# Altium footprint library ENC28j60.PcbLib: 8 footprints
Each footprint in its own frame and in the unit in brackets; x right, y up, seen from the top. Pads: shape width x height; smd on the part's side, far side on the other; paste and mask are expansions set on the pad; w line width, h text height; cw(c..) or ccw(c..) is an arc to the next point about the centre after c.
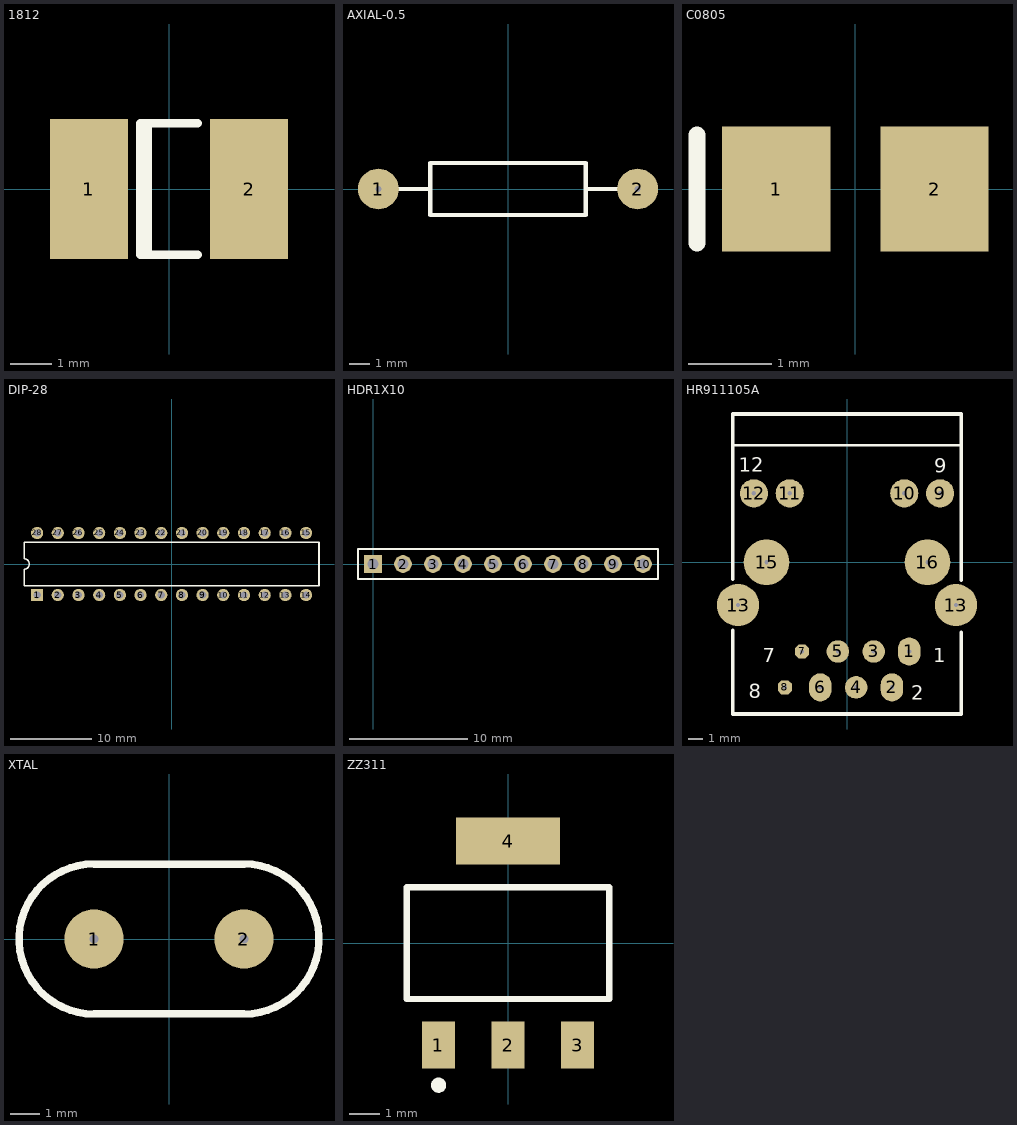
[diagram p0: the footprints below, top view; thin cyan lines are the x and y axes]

## 1812 [mm] "Chip Capacitor; Body 4.5 x 3.2 mm (LxW typ)"
height 1.1
pads (2):
  rect 1.9x3.4 smd: 1(-1.95,0) 2(1.95,0)
Top Overlay:
  lines w0.2: -0.51,-1.6 -0.51,1.6 ; 0.7,-1.6 -0.7,-1.6 -0.7,1.6 0.7,1.6

## AXIAL-0.5 [mm] "Semiconductor Resistor; 2 Leads"
height 2.54
pads (2):
  round 2 hole 0.3: 1(-6.35,0) 2(6.35,0)
Top Overlay:
  lines w0.2: -5.334,0 -3.81,0 ; 3.81,0 5.334,0 ; -3.81,-1.27 3.81,-1.27 3.81,1.27 -3.81,1.27 -3.81,-1.27

## C0805 [mm] "Chip Capacitor; Body 2.0 x 1.2 mm (LxW typ)"
height 1.1
pads (2):
  rect 1.3x1.5 smd: 1(-0.95,0) 2(0.95,0)
Top Overlay:
  lines w0.2: -1.9,-0.65 -1.9,0.65

## DIP-28 [mm] "DIP; 28 Leads; Row Spacing 7.62 mm; Pitch 2.54 mm"
height 5.33
pads (28):
  rect 1.5x1.5 hole 0.9: 1(-16.51,-3.81)
  round 1.5 hole 0.9: 2(-13.97,-3.81) 3(-11.43,-3.81) 4(-8.89,-3.81) 5(-6.35,-3.81) 6(-3.81,-3.81) 7(-1.27,-3.81) 8(1.27,-3.81) 9(3.81,-3.81) 10(6.35,-3.81) 11(8.89,-3.81) 12(11.43,-3.81) 13(13.97,-3.81) 14(16.51,-3.81) 15(16.51,3.81) 16(13.97,3.81) 17(11.43,3.81) 18(8.89,3.81) 19(6.35,3.81) 20(3.81,3.81) 21(1.27,3.81) 22(-1.27,3.81) 23(-3.81,3.81) 24(-6.35,3.81) 25(-8.89,3.81) 26(-11.43,3.81) 27(-13.97,3.81) 28(-16.51,3.81)
Top Overlay:
  lines w0.2: -18.1,-2.65 18.1,-2.65 18.1,2.65 -18.1,2.65 -18.1,0.635 cw(c-18.1,0) -18.1,-0.635 -18.1,-2.65

## HDR1X10 [mm] "Connector; Header; 10 Position"
height 5.08
pads (10):
  rect 1.5x1.5 hole 0.9: 1(0,0)
  round 1.5 hole 0.9: 2(2.54,0) 3(5.08,0) 4(7.62,0) 5(10.16,0) 6(12.7,0) 7(15.24,0) 8(17.78,0) 9(20.32,0) 10(22.86,0)
Top Overlay:
  lines w0.2: -1.27,-1.27 24.13,-1.27 24.13,1.27 0.635,1.27 -1.27,1.27 -1.27,-1.27

## HR911105A [mm] "HR911105A 带网络变压器及LED的一体化RJ45插座"
height 13.4
pads (16):
  oval 1.6x2 hole 0.3: 1(4.425,-6.35) 2(3.2,-8.9) 6(-1.9,-8.9)
  round 1.6 hole 0.3: 3(1.9,-6.35) 4(0.65,-8.9) 5(-0.65,-6.35)
  oct 1x1 hole 0.3: 7(-3.2,-6.35) 8(-4.425,-8.9)
  round 2 hole 0.3: 9(6.625,4.9) 10(4.075,4.9) 11(-4.075,4.9) 12(-6.625,4.9)
  round 3 hole 0.3: 13(-7.75,-3.05) 13(7.75,-3.05)
  round 3.25 hole 0.3: 15(-5.725,0) 16(5.725,0)
Top Overlay:
  lines w0.2: -8.128,8.325 8.078,8.325
  lines w0.254: -8.128,-4.847 -8.128,-10.795 8.128,-10.795 8.128,-4.978 ; -8.128,-1.203 -8.128,10.541 8.128,10.541 8.128,-1.297
  text "12" at -7.7,6.425 h1
  text "9" at 6.2,6.35 h1
  text "1" at 6.125,-7.125 h1
  text "7" at -5.975,-7.1 h1
  text "2" at 4.572,-9.779 h1
  text "8" at -6.975,-9.675 h1

## XTAL [mm] "晶振"
height 5.08
pads (2):
  round 2 hole 0.3: 1(-2.54,0) 2(2.54,0)
Top Overlay:
  lines w0.254: -2.54,-2.54 cw(c-2.54,0) -2.54,2.54 2.54,2.54 cw(c2.54,0) 2.54,-2.54 -2.54,-2.54

## ZZ311 [mm] "SOT-223/SC-73; 4 Leads; Body 6.7 x 7.3 mm, inc. leads (LxW max)"
height 1.8
pads (4):
  rect 1.1x1.55 smd: 1(-2.3,-3.375) 2(0,-3.375) 3(2.3,-3.375)
  rect 3.45x1.55 smd: 4(0,3.375)
Top Overlay:
  circle w0.25: c-2.3,-4.7 r0.125
  lines w0.2: -3.35,-1.85 3.35,-1.85 3.35,1.85 -3.35,1.85 -3.35,-1.85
